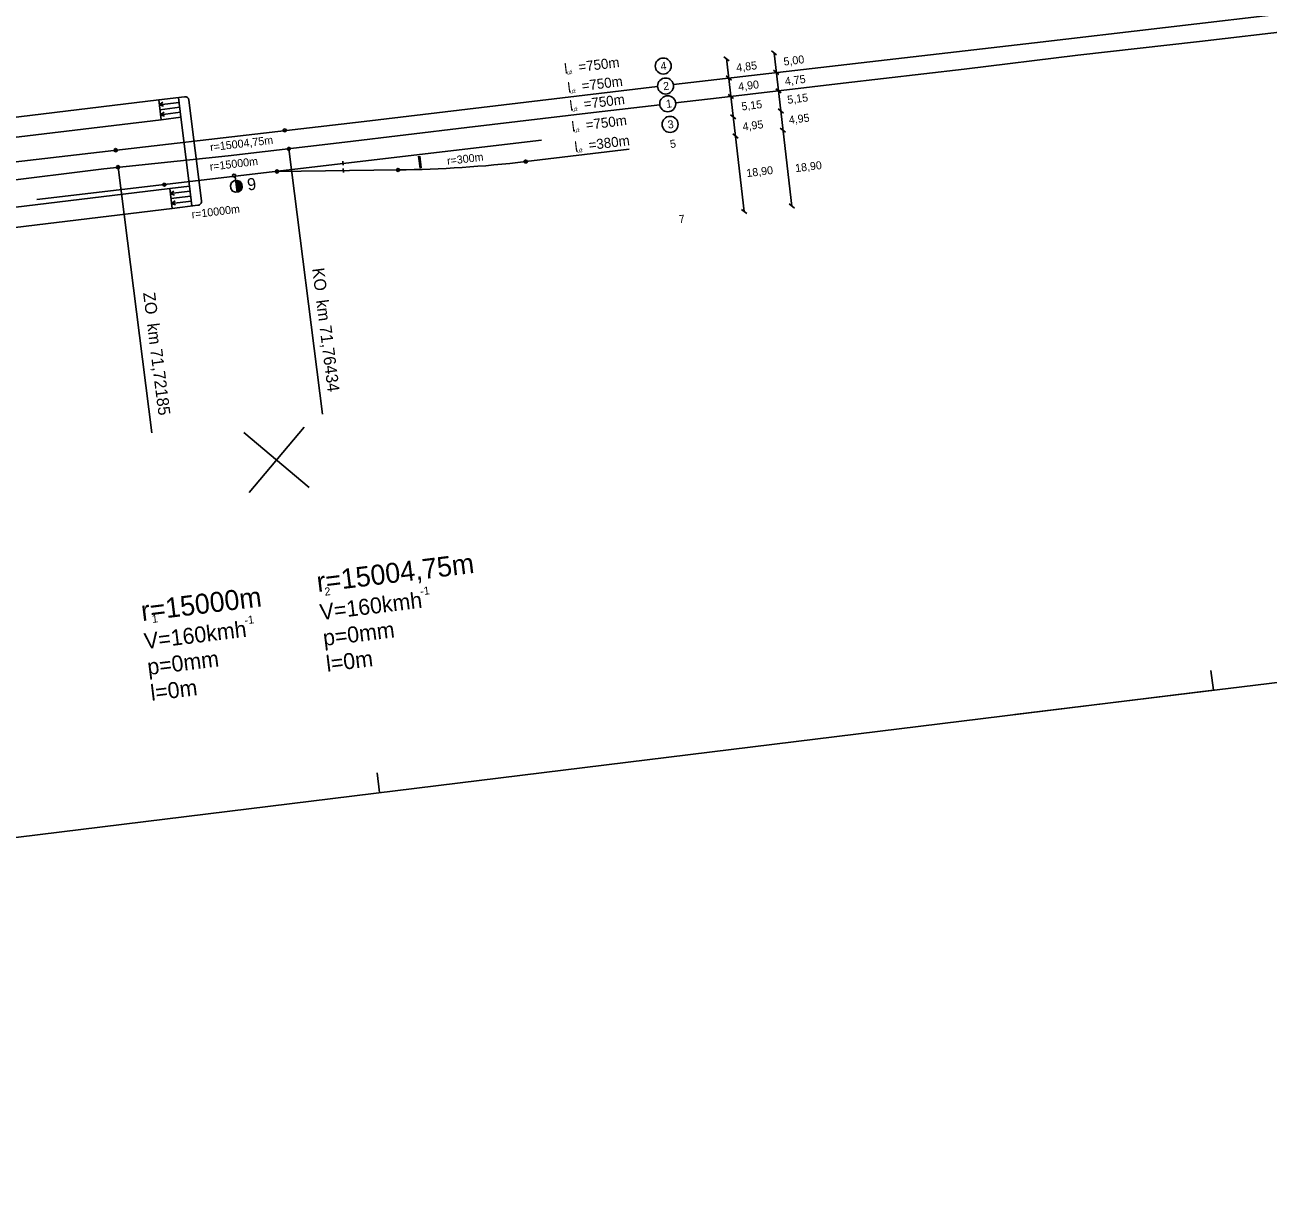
# Model space of a CAD drawing. Extents: x -559083 to -556962, y -1276579 to -1276028.
# Drawn here: x -558301.5 to -557990.7, y -1276578.6 to -1276284.3 of the extents above; entities that cross this region are included whole.
import ezdxf

# ---------------------------------------------------------------- set-up
doc = ezdxf.new("R2010")
doc.units = 0
for name, color, linetype in [('kolaj s', 7, 'Continuous'), ('popis 25', 7, 'Continuous'), ('popis 50', 7, 'Continuous'), ('ram vykresu', 7, 'Continuous'), ('stavby', 7, 'Continuous')]:
    doc.layers.add(name, color=color, linetype=linetype)

msp = doc.modelspace()

# ---------------------------------------------------------------- linework, layer by layer
at = {"layer": 'kolaj s'}
for p, q in [((-557965.05, -1276278.93), (-558049.14, -1276288.8)), ((-558007.88, -1276288.49), (-557976.35, -1276284.79)), ((-558049.14, -1276288.8), (-558139.36, -1276299.24)), ((-558038.32, -1276291.87), (-558007.88, -1276288.49)), ((-558066.69, -1276295.36), (-558038.32, -1276291.87)), ((-558096.98, -1276298.88), (-558066.69, -1276295.36)), ((-558143.33, -1276299.7), (-558216.7, -1276308.45)), ((-558127.92, -1276302.55), (-558096.98, -1276298.88)), ((-558159.34, -1276306.22), (-558142.8, -1276304.29)), ((-558138.82, -1276303.82), (-558127.92, -1276302.55)), ((-558191.01, -1276309.96), (-558159.34, -1276306.22)), ((-558216.7, -1276308.45), (-558304.47, -1276318.63)), ((-558236.54, -1276310.69), (-558236.54, -1276310.69)), ((-558221.55, -1276313.63), (-558191.01, -1276309.96)), ((-558172.39, -1276313.16), (-558298.54, -1276328.01)), ((-558250.68, -1276317.04), (-558221.55, -1276313.63)), ((-558281.77, -1276320.27), (-558250.68, -1276317.04)), ((-558278.8, -1276315.65), (-558278.8, -1276315.65)), ((-558235.52, -1276315.31), (-558235.52, -1276315.31)), ((-558176.29, -1276318.5), (-558150.45, -1276315.41)), ((-558278.22, -1276319.91), (-558278.22, -1276319.91)), ((-558222.05, -1276318.43), (-558221.93, -1276319.42)), ((-558221.99, -1276318.93), (-558221.99, -1276318.93)), ((-558176.29, -1276318.5), (-558176.29, -1276318.5)), ((-558310.43, -1276323.91), (-558281.77, -1276320.27)), ((-558249.19, -1276321.99), (-558249.19, -1276321.99)), ((-558238.48, -1276320.96), (-558208.21, -1276320.59)), ((-558238.48, -1276320.96), (-558238.48, -1276320.96)), ((-558221.94, -1276320.2), (-558221.82, -1276321.2)), ((-558221.88, -1276320.7), (-558221.88, -1276320.7)), ((-558208.21, -1276320.59), (-558208.21, -1276320.59)), ((-558266.64, -1276324.26), (-558266.64, -1276324.26))]:
    msp.add_line(p, q, dxfattribs=at)
for points in [[(-558236.59, -1276310.29), (-558236.22, -1276310.44), (-558236.17, -1276310.84), (-558236.49, -1276311.08), (-558236.86, -1276310.92), (-558236.91, -1276310.53), (-558236.59, -1276310.29)], [(-558278.85, -1276315.26), (-558278.48, -1276315.41), (-558278.43, -1276315.81), (-558278.75, -1276316.05), (-558279.12, -1276315.89), (-558279.17, -1276315.5), (-558278.85, -1276315.26)], [(-558235.56, -1276314.91), (-558235.2, -1276315.07), (-558235.15, -1276315.46), (-558235.47, -1276315.71), (-558235.83, -1276315.55), (-558235.88, -1276315.15), (-558235.56, -1276314.91)], [(-558278.27, -1276319.51), (-558277.9, -1276319.66), (-558277.85, -1276320.06), (-558278.17, -1276320.3), (-558278.54, -1276320.14), (-558278.59, -1276319.75), (-558278.27, -1276319.51)], [(-558176.25, -1276318.9), (-558176.61, -1276318.74), (-558176.66, -1276318.34), (-558176.34, -1276318.1), (-558175.97, -1276318.26), (-558175.93, -1276318.66), (-558176.25, -1276318.9)], [(-558249.24, -1276321.6), (-558248.87, -1276321.75), (-558248.82, -1276322.15), (-558249.14, -1276322.39), (-558249.51, -1276322.23), (-558249.56, -1276321.84), (-558249.24, -1276321.6)], [(-558238.43, -1276321.36), (-558238.8, -1276321.2), (-558238.84, -1276320.8), (-558238.52, -1276320.56), (-558238.16, -1276320.72), (-558238.11, -1276321.12), (-558238.43, -1276321.36)], [(-558208.16, -1276320.99), (-558208.53, -1276320.83), (-558208.57, -1276320.44), (-558208.26, -1276320.19), (-558207.89, -1276320.35), (-558207.84, -1276320.75), (-558208.16, -1276320.99)], [(-558266.69, -1276323.87), (-558266.32, -1276324.02), (-558266.27, -1276324.42), (-558266.59, -1276324.66), (-558266.96, -1276324.5), (-558267.01, -1276324.11), (-558266.69, -1276323.87)]]:
    msp.add_lwpolyline(points, dxfattribs=at)
msp.add_arc((-558211.85, -1276020.61), 300, 270.6947, 276.806, dxfattribs=at)
at = {"layer": 'popis 25'}
for p, q in [((-558113.57, -1276291.8), (-558114.9, -1276290.77)), ((-558114.22, -1276291.38), (-558109.8, -1276329.61)), ((-558125.42, -1276293.3), (-558126.75, -1276292.27)), ((-558126.09, -1276292.75), (-558121.67, -1276330.98)), ((-558124.87, -1276298.1), (-558126.19, -1276297.07)), ((-558113.01, -1276296.7), (-558114.33, -1276295.67)), ((-558112.47, -1276301.34), (-558113.79, -1276300.31)), ((-558124.33, -1276302.72), (-558125.66, -1276301.69)), ((-558123.75, -1276307.8), (-558125.07, -1276306.77)), ((-558111.89, -1276306.36), (-558113.21, -1276305.33)), ((-558111.33, -1276311.15), (-558112.66, -1276310.12)), ((-558123.19, -1276312.62), (-558124.51, -1276311.59)), ((-558203.07, -1276317.15), (-558202.72, -1276320.12)), ((-558202.76, -1276317.11), (-558202.4, -1276320.08)), ((-558109.14, -1276330.11), (-558110.46, -1276329.08)), ((-558121.01, -1276331.5), (-558122.33, -1276330.47))]:
    msp.add_line(p, q, dxfattribs=at)
at = {"layer": 'popis 50'}
for p, q in [((-558235.49, -1276315.28), (-558227.08, -1276381.65)), ((-558278.19, -1276319.91), (-558269.78, -1276386.27)), ((-558248.93, -1276322.2), (-558248.93, -1276322.2)), ((-558248.93, -1276322.2), (-558248.46, -1276326.13)), ((-558231.72, -1276384.89), (-558245.46, -1276401.26)), ((-558230.4, -1276399.94), (-558246.78, -1276386.2))]:
    msp.add_line(p, q, dxfattribs=at)
msp.add_lwpolyline([(-558248.06, -1276326.08), (-558248.86, -1276326.17), (-558249.58, -1276325.85), (-558250.02, -1276325.26), (-558250.12, -1276324.46), (-558249.81, -1276323.76), (-558249.2, -1276323.29), (-558248.41, -1276323.2), (-558247.7, -1276323.51), (-558247.24, -1276324.13), (-558247.15, -1276324.9), (-558247.45, -1276325.61), (-558248.06, -1276326.08), (-558247.84, -1276325.8), (-558248.34, -1276325.86), (-558248.38, -1276325.56), (-558247.53, -1276325.46), (-558247.42, -1276325.15), (-558248.41, -1276325.26), (-558248.45, -1276324.97), (-558247.31, -1276324.83), (-558247.34, -1276324.53), (-558248.48, -1276324.67), (-558248.52, -1276324.37), (-558247.38, -1276324.24), (-558247.56, -1276323.95), (-558248.55, -1276324.07), (-558248.59, -1276323.78), (-558247.8, -1276323.68), (-558248.18, -1276323.42), (-558248.62, -1276323.48)], dxfattribs=at)
for centre in [(-558141.92, -1276294.6), (-558141.33, -1276299.6), (-558140.81, -1276304.04), (-558140.21, -1276309.19)]:
    msp.add_circle(centre, 2, dxfattribs=at)
at = {"layer": 'ram vykresu'}
for p, q in [((-556962.22, -1276322.7), (-558054.04, -1276456.76)), ((-558004.4, -1276450.67), (-558005.01, -1276445.7)), ((-558004.4, -1276450.67), (-559046.57, -1276578.63)), ((-558212.83, -1276476.26), (-558213.44, -1276471.3))]:
    msp.add_line(p, q, dxfattribs=at)
at = {"layer": 'stavby'}
for p, q in [((-558516.24, -1276333.09), (-558268.05, -1276303.06)), ((-558268.05, -1276303.06), (-558261.61, -1276302.27)), ((-558267.44, -1276308.02), (-558268.05, -1276303.06)), ((-558267.01, -1276303.68), (-558267.9, -1276304.3)), ((-558267.9, -1276304.3), (-558262.94, -1276303.69)), ((-558266.88, -1276304.68), (-558267.9, -1276304.3)), ((-558263.09, -1276302.45), (-558262.48, -1276307.41)), ((-558260.49, -1276303.14), (-558257.36, -1276328.29)), ((-558267.75, -1276305.54), (-558262.79, -1276304.93)), ((-558266.7, -1276306.16), (-558267.6, -1276306.78)), ((-558267.6, -1276306.78), (-558262.63, -1276306.17)), ((-558266.58, -1276307.17), (-558267.6, -1276306.78)), ((-558262.48, -1276307.41), (-558267.44, -1276308.02)), ((-558262.48, -1276307.41), (-558260.34, -1276324.63)), ((-558267.45, -1276308.02), (-558515.64, -1276338.06)), ((-558265.3, -1276325.24), (-558260.34, -1276324.63)), ((-558264.26, -1276325.86), (-558265.15, -1276326.48)), ((-558265.15, -1276326.48), (-558260.19, -1276325.87)), ((-558260.34, -1276324.63), (-558259.73, -1276329.59)), ((-558264.13, -1276326.86), (-558265.15, -1276326.48)), ((-558265, -1276327.72), (-558260.03, -1276327.11)), ((-558263.95, -1276328.34), (-558264.84, -1276328.96)), ((-558264.84, -1276328.96), (-558259.88, -1276328.35)), ((-558263.83, -1276329.34), (-558264.84, -1276328.96)), ((-558258.23, -1276329.41), (-558264.69, -1276330.2))]:
    msp.add_line(p, q, dxfattribs=at)
msp.add_lwpolyline([(-558482.85, -1276356.6), (-558512.89, -1276360.24), (-558513.49, -1276355.27), (-558265.3, -1276325.24), (-558264.7, -1276330.2), (-558427.9, -1276349.95)], dxfattribs=at)
for centre, start, end in [((-558261.48, -1276303.26), 7.0937, 97.0431), ((-558258.35, -1276328.41), 277.0108, 7.0813)]:
    msp.add_arc(centre, 1, start, end, dxfattribs=at)

# ---------------------------------------------------------------- texts
at = {"layer": 'popis 25'}
for s, height, rotation, p in [('5,00', 2, 7, (-558111.74, -1276294.51)), ('l   =750m', 2.5, 7, (-558166.49, -1276296.53)), ('4,85', 2, 7, (-558123.54, -1276296.02)), ('už', 1, 7, (-558166, -1276296.75)), ('l   =750m', 2.5, 7, (-558165.67, -1276301.26)), ('4,90', 2, 7, (-558123.06, -1276300.77)), ('4,75', 2, 7, (-558111.41, -1276299.43)), ('už', 1, 7, (-558165.18, -1276301.48)), ('5,15', 2, 7, (-558110.79, -1276304.06)), ('l   =750m', 2.5, 7, (-558165.16, -1276305.78)), ('5,15', 2, 7, (-558122.26, -1276305.73)), ('l   =750m', 2.5, 7, (-558164.65, -1276311.02)), ('už', 1, 7, (-558164.67, -1276306)), ('4,95', 2, 7, (-558110.42, -1276309.1)), ('už', 1, 7, (-558164.16, -1276311.24)), ('4,95', 2, 7, (-558121.97, -1276310.76)), ('r=15004,75m', 2, 6.8, (-558255.08, -1276315.91)), ('l   =380m', 2.5, 7, (-558163.93, -1276316.06)), ('r=300m', 2, 6.8, (-558195.85, -1276319.34)), ('už', 1, 7, (-558163.44, -1276316.28)), ('r=15000m', 2, 6.8, (-558255.17, -1276320.77)), ('18,90', 2, 7, (-558121.03, -1276322.39)), ('18,90', 2, 7, (-558108.82, -1276321.14)), ('r=10000m', 2, 6.8, (-558259.7, -1276332.7))]:
    msp.add_text(s, height=height, rotation=rotation, dxfattribs=at).set_placement(p)
at = {"layer": 'popis 50'}
for s, height, rotation, p in [('4', 2, 7, (-558142.49, -1276295.67)), ('2', 2, 7, (-558141.82, -1276300.67)), ('1', 2, 7, (-558141.12, -1276305.09)), ('3', 2, 7, (-558140.69, -1276310.26)), ('5', 2, 7, (-558140.12, -1276315.12)), ('9', 3, 7, (-558245.74, -1276325.74)), ('7', 2, 7, (-558137.91, -1276333.92)), ('KO  km 71,76434', 3, 277.2222, (-558229.7, -1276345.25)), ('ZO  km 71,72185', 3, 277.2222, (-558271.96, -1276351.34)), ('r=15004,75m', 5, 7, (-558228.26, -1276426.12)), ('r=15000m', 5, 7, (-558272.16, -1276433.38)), ('2', 2, 7, (-558226.48, -1276427.03)), ('-1', 2, 7, (-558202.58, -1276426.94)), ('V=160kmh', 4, 7, (-558227.53, -1276433.15)), ('1', 2, 7, (-558269.63, -1276433.83)), ('-1', 2, 7, (-558246.49, -1276434.19)), ('V=160kmh', 4, 7, (-558271.44, -1276440.4)), ('p=0mm', 4, 7, (-558226.74, -1276439.6)), ('l=0m', 4, 7, (-558225.95, -1276446.05)), ('p=0mm', 4, 7, (-558270.65, -1276446.86)), ('l=0m', 4, 7, (-558269.85, -1276453.31))]:
    msp.add_text(s, height=height, rotation=rotation, dxfattribs=at).set_placement(p)

doc.saveas('drawing.dxf')
